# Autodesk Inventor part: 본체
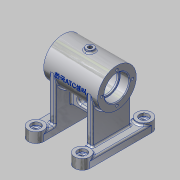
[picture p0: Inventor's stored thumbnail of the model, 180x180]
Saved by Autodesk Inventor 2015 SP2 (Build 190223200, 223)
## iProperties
Created: 2015-11
Part Number: 본체
Material: 알루미늄 6061
Document SubType Name: Modeling
Designer: AMC
Density: 2.7 g/cm^3
Appearance: 알루미늄 - 평지
Mass: 356.28 g
Surface Area: 460.41 cm^2
Volume: 131.956 cm^3
Author: AMC
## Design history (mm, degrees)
sketch "스케치1"
  geometry: C1 r 25 at (0, 0); 1 further point
  constraints: 1 centre point, 1 coincident
  dimensions: "d0" = 50 diameter of C1
extrude "돌출1" new body sketch "스케치1" stored distance "d1" = 70; taper "d2" = 0 deg
node "작업 평면1"
sketch "스케치2"
  geometry: L1 (0, -35)-(0, 35) reference; L2 (30, 40)-(30, -40); L3 (20, 40)-(20, -40); L4 (40, -40)-(40, 40); L5 (-30, 40)-(-30, -40); L6 (-20, 40)-(-20, -40); L7 (-40, -40)-(-40, 40); A1 r 10 centre (30, 40) between (40, 40) and (20, 40); A2 r 10 centre (30, -40) between (20, -40) and (40, -40); A3 r 10 centre (-30, -40) between (-40, -40) and (-20, -40); A4 r 10 centre (-30, 40) between (-20, 40) and (-40, 40); 2 further points
  constraints: 16 end point, 8 point on circle, 6 symmetric about line, 4 centre point, 4 tangent, 1 horizontal alignment, 1 midpoint, 1 parallel, 1 vertical, 2 other
  dimensions: "d7" = 40 distance from line of L4 point (0, 0); "d8" = 80 distance of L2.start L2.end; "d9" = 20 distance between parallel lines of L4 L3
extrude "돌출2" join sketch "스케치2" distance "d10" = 10; taper "d11" = 0 deg
sketch "스케치3"
  geometry: L1 (-40, 40)-(-40, -40) reference; L2 (-20, -40)-(-20, 40) reference; L3 (20, 40)-(20, -40) reference; L4 (40, -40)-(40, 40) reference; C1 r 10 at (-30, -40); A1 r 10 centre (-30, -40) between (-40, -40) and (-20, -40) reference; A2 r 10 centre (-30, 40) between (-20, 40) and (-40, 40) reference; A3 r 10 centre (30, -40) between (20, -40) and (40, -40) reference; A4 r 10 centre (30, 40) between (40, 40) and (20, 40) reference; 1 further point
  constraints: 1 centre point, 1 coincident, 1 concentric
extrude "돌출3" join sketch "스케치3" distance "d12" = 3; taper "d13" = 0 deg
sketch "스케치4"
  geometry: L1 (40, -55)-(20, -55) reference; L2 (40, -68)-(20, -68) reference; L3 (40, -68)-(40, -58) reference; L4 (20, -58)-(40, -58) reference; L5 (20, -68)-(20, -58) reference; L6 (35, -25)-(35, 25) reference; L7 (-35, 25)-(-35, -25) reference; L8 (20, -58)-(28, -58); L9 (28, -58)-(28, 0); L10 (28, 0)-(20, 0); L11 (20, 0)-(20, -58); 1 further point
  constraints: 8 end point, 2 parallel, 1 horizontal, 1 horizontal alignment, 1 perpendicular
  dimensions: "d21" = 8 distance of L10.end L9.end
extrude "돌출4" join sketch "스케치4" stored distance "d22" = 50; taper "d23" = 0 deg
node "작업 평면2"
sketch "스케치5"
  geometry: C1 r 5 at (0, 0); 1 further point
  constraints: 1 centre point, 1 coincident
  dimensions: "d25" = 10 diameter of C1
extrude "돌출5" join sketch "스케치5" stored distance "d26" = 50; taper "d27" = 0 deg
sketch "스케치6"
  geometry: L1 (56, 0)-(-56, 0) reference; L2 (35, 0)-(35, 16); L3 (35, 16)-(23, 16); L4 (23, 16)-(23, 14); L5 (23, 14)-(21, 14); L6 (21, 14)-(21, 21); L7 (21, 21)-(-21, 21); L8 (-21, 21)-(-21, 14); L9 (-21, 14)-(-23, 14); L10 (-23, 14)-(-23, 16); L11 (-23, 16)-(-35, 16); L12 (-35, 16)-(-35, 0); L13 (35, -25)-(35, 25) reference; L14 (-35, 25)-(-35, -25) reference; 2 further points
  constraints: 22 end point, 8 perpendicular, 4 collinear, 2 point on line, 2 vertical, 1 midpoint, 1 parallel, 1 vertical alignment
  dimensions: "d29" = 32 diameter of L3 L1; "d30" = 28 diameter of L5 L1; "d31" = 42 diameter of L7 L1; "d32" = 12 distance between parallel lines of L2 L4; "d33" = 42 distance between parallel lines of L8 L6; "d34" = 12 distance between parallel lines of L14 L10
revolve "회전1" sketch "스케치6" stored, may be unused: angle "d35" = 90 deg
sketch "스케치7"
  geometry: 2 further points
  constraints: 1 vertical alignment
  dimensions: "d36" = 20 distance of point (0, 0) point (0, 20)
hole "구멍1" sketch "스케치7" at (0, 20) diameter "d37" = 3.242; stored, may be unused: countersink angle "d41" = 90 deg, drill point angle "d43" = 118 deg; dims "d38" = 8, "d39" = 4, "d40" = 2, "d42" = 10
node "작업 평면4"
sketch "스케치8"
  geometry: L1 (-28, -4)-(28, -4); L2 (28, -4)-(28, 4); L3 (28, 4)-(-28, 4); L4 (-28, 4)-(-28, -4); L5 (-28, -4)-(28, 4); L6 (28, -4)-(-28, 4); L7 (-28, -25)-(-28, 25) reference; L8 (28, 25)-(28, -25) reference; 1 further point
  constraints: 12 end point, 2 midpoint, 2 parallel, 1 collinear, 1 horizontal, 1 perpendicular
  dimensions: "d48" = 8 distance between parallel lines of L1 L3
extrude "돌출6" join sketch "스케치8" stored distance "d49" = 50; taper "d50" = 0 deg
sketch "스케치9"
  geometry: L1 (12, 10)-(28, 10); L2 (12, 6.5)-(28, 6.5); L3 (28, 13.5)-(12, 13.5); L4 (60, -23)-(40, -23) reference; A1 r 3.5 centre (12, 10) between (12, 13.5) and (12, 6.5); A2 r 3.5 centre (28, 10) between (28, 6.5) and (28, 13.5); 2 further points
  constraints: 8 end point, 4 point on circle, 4 tangent, 2 centre point, 1 horizontal, 1 midpoint, 1 parallel, 1 vertical alignment
  dimensions: "d51" = 33 distance from line of L4 point (20, 10); "d56" = 7 distance between parallel lines of L2 L3; "d114" = 23 dimension on A1 A2
extrude "돌출7" cut sketch "스케치9" stored distance "d57" = 50; taper "d58" = 0 deg
hole "구멍2" diameter "d61" = 5.188; stored, may be unused: countersink angle "d65" = 90 deg, drill point angle "d67" = 118 deg; dims "d59" = 10, "d60" = 10, "d62" = 12, "d63" = 4, "d64" = 2, "d66" = 16
sketch "스케치10"
  geometry: L1 (0, -87.2)-(0, 47.2) reference; L2 (0, 0)-(-14, -24.249)
  constraints: 2 end point
  dimensions: "d70" = 28 distance of L2.start L2.end; "d73" = 30 deg angle of L1 L2
node "작업 평면6"
sketch "스케치11"
  geometry: C1 r 6 at (0, 0); 1 further point
  constraints: 1 centre point, 1 coincident
  dimensions: "d74" = 12 diameter of C1
extrude "돌출8" join sketch "스케치11" stored distance "d75" = 50; taper "d76" = 0 deg
hole "구멍3" diameter "d79" = 5.188; stored, may be unused: countersink angle "d83" = 90 deg, drill point angle "d85" = 118 deg; dims "d77" = 10, "d78" = 10, "d80" = 12, "d81" = 4, "d82" = 2, "d84" = 16
sketch "스케치12"
  geometry: L1 (-21.03, 3.044)-(21.03, 3.044); L2 (21.03, 3.044)-(21.03, -3.044); L3 (21.03, -3.044)-(-21.03, -3.044); L4 (-21.03, -3.044)-(-21.03, 3.044); L5 (0, 3.044)-(0, -3.044); L6 (-21.03, 0)-(21.03, 0); L7 (-20, -68)-(-40, -68) reference; L8 (35, 25)-(-35, 25) reference; L9 (-35, 25)-(-35, -25) reference; 1 further point
  constraints: 4 end point, 4 midpoint, 2 other
  dimensions: "d86" = 42.05917 distance between parallel lines of L2 L4; "d87" = 6.08806 distance between parallel lines of L3 L1; "d89" = 25 distance between parallel lines of L8 L6 (derived); "d90" = 35 distance between parallel lines of L5 L9 (derived)
feature "엠보싱1" sketch "스케치12" dims "d91" = 0.5, "d92" = 0
fillet "모깎기1" dims "d93" = 2
hole "구멍4" diameter "d96" = 6; stored, may be unused: countersink angle "d100" = 90 deg, drill point angle "d102" = 118 deg; dims "d94" = 10, "d95" = 10, "d97" = 12, "d98" = 12, "d99" = 4, "d101" = 16
chamfer "모따기1" distance "d109" = 1; stored, may be unused: second distance "d110" = 2, angle "d111" = 45 deg
fillet "모깎기2" dims "d112" = 0.3
fillet "모깎기3" dims "d113" = 3
node "솔리드1"
pattern_linear "직사각형 패턴1" dims "d16" = 80
mirror "대칭1"
pattern_circular "원형 패턴1" dims angle "d45" = 360 deg
mirror "대칭2"
pattern_linear "직사각형 패턴2" dims "d105" = 80
node "투영된 루프1"
node "투영된 루프2"
node "투영된 루프3"
node "투영된 루프4"
other parameters: "d3" = -68, "d24" = 28, "d47" = -45
